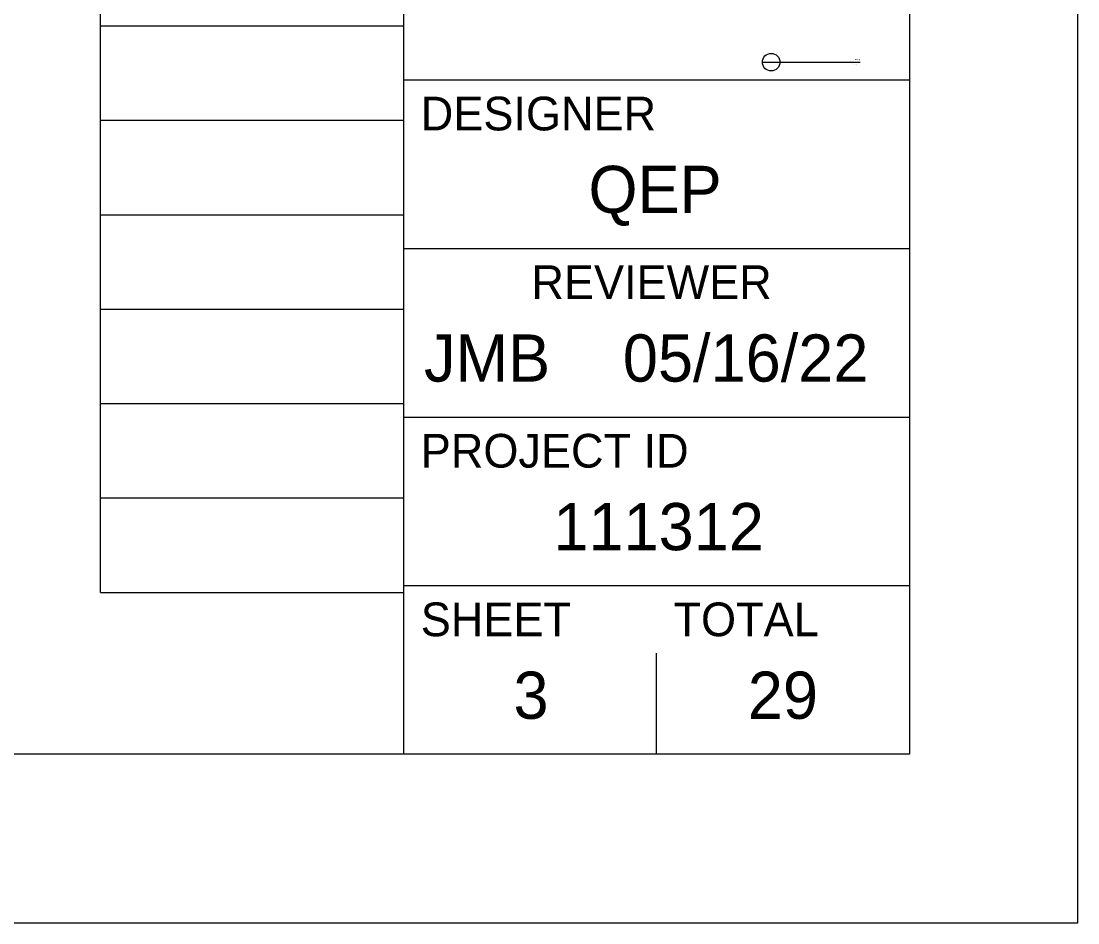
# Model space of a CAD drawing. Extents: x 0 to 58.9, y 0 to 22.
# Drawn here: x 30.864 to 34, y 0 to 2.674 of the extents above; entities that cross this region are included whole.
import ezdxf

# ---------------------------------------------------------------- set-up
doc = ezdxf.new("R2010")
doc.units = 0
for name, color, linetype in [('CS-ALGN-CNTR', 7, 'Continuous'), ('CS-ALGN-TEXT', 7, 'Continuous'), ('CS-ANNO', 7, 'Continuous'), ('CS-ANNO-MATC-MASK', 7, 'Continuous')]:
    doc.layers.add(name, color=color, linetype=linetype)

msp = doc.modelspace()

# ---------------------------------------------------------------- linework, layer by layer
at = {"layer": 'CS-ALGN-CNTR'}
msp.add_lwpolyline([(0, 0), (34, 0), (34, 22), (0, 22)], close=True, dxfattribs=at)
at = {"layer": 'CS-ALGN-TEXT'}
for p, q in [((32, 0.5), (32, 21.5)), ((32, 2.5), (33.5, 2.5)), ((32, 2), (33.5, 2)), ((32, 1.5), (33.5, 1.5)), ((32, 1), (33.5, 1))]:
    msp.add_line(p, q, dxfattribs=at)
msp.add_lwpolyline([(1.5, 21.5), (33.5, 21.5), (33.5, 0.5), (1.5, 0.5)], close=True, dxfattribs=at)
at = {"layer": 'CS-ANNO'}
for p, q in [((32.75, 0.5), (32.75, 0.8)), ((32.375, 0.675), (32.375, 0.675))]:
    msp.add_line(p, q, dxfattribs=at)
at = {"layer": 'CS-ANNO-MATC-MASK'}
for p, q in [((31.1, 0.98), (31.1, 21.14)), ((32, 0.98), (32, 21.14)), ((31.1, 2.66), (32, 2.66)), ((33.0636, 2.5523), (33.1157, 2.5523)), ((33.0899, 2.5523), (33.3542, 2.5523)), ((31.1, 2.38), (32, 2.38)), ((31.1, 2.1), (32, 2.1)), ((31.1, 1.82), (32, 1.82)), ((31.1, 1.54), (32, 1.54)), ((31.1, 1.26), (32, 1.26)), ((31.1, 0.98), (32, 0.98))]:
    msp.add_line(p, q, dxfattribs=at)
msp.add_circle((33.0897, 2.5523), 0.026, dxfattribs=at)

# ---------------------------------------------------------------- texts
at = {"layer": 'CS-ANNO'}
for s, height, p in [('DESIGNER', 0.1, (32.05, 2.35)), ('QEP', 0.14, (32.5477, 2.105)), ('REVIEWER', 0.1, (32.3783, 1.85)), ('JMB', 0.14, (32.0596, 1.605)), ('05/16/22', 0.14, (32.6497, 1.605)), ('PROJECT ID', 0.1, (32.05, 1.35)), ('111312', 0.14, (32.4435, 1.105)), ('SHEET', 0.1, (32.05, 0.85)), ('TOTAL', 0.1, (32.8, 0.85)), ('3', 0.14, (32.3251, 0.605)), ('29', 0.14, (33.0206, 0.605))]:
    msp.add_text(s, height=height, dxfattribs=at).set_placement(p)
at = {"layer": 'CS-ANNO-MATC-MASK'}
for s, p in [('1', (33.0888, 2.5589)), ('Drawing', (33.3372, 2.5589)), ('1:2', (33.3372, 2.5425))]:
    msp.add_text(s, height=0.00328, dxfattribs=at).set_placement(p)

doc.saveas('drawing.dxf')
